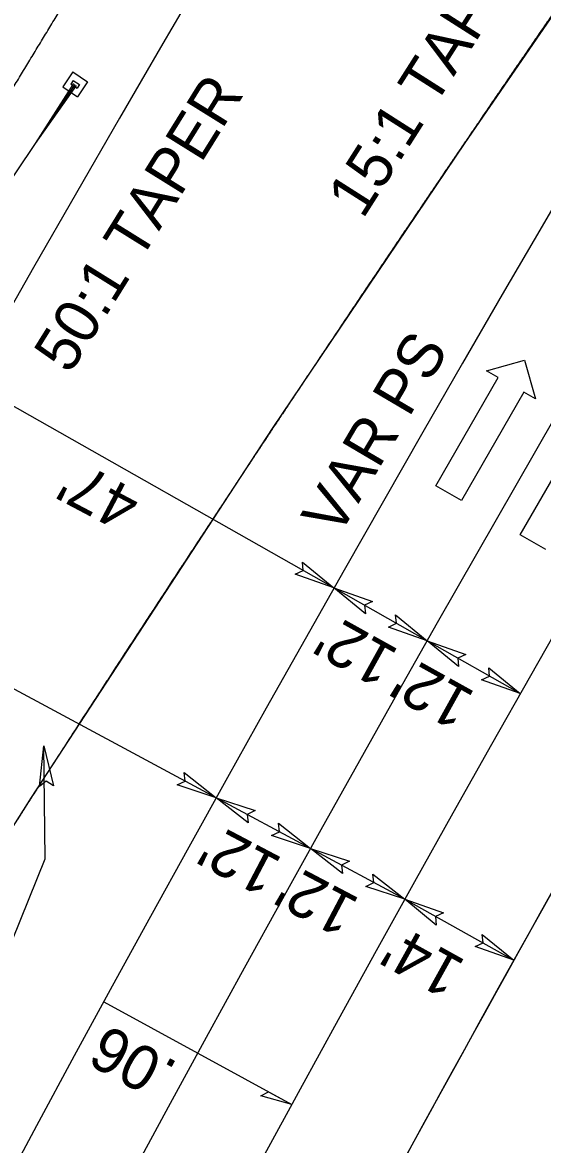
# Model space of a CAD drawing. Extents: x 2389694 to 2405615, y 546931 to 573532.
# Drawn here: x 2395690.8 to 2395749, y 557120.4 to 557246.1 of the extents above; entities that cross this region are included whole.
import ezdxf

# ---------------------------------------------------------------- set-up
doc = ezdxf.new("R2010")
doc.units = 0
for name, color, linetype in [('Prop Cable Guiderail Anchor Unit CELL', 7, 'Continuous'), ('Prop Dimension', 7, 'Continuous'), ('Prop Dimension Text', 7, 'Continuous'), ('Prop DSN Text', 7, 'Continuous'), ('Prop EOT', 7, 'Continuous'), ('Prop Guardrail', 7, 'Continuous'), ('Prop Horizontal Alignment', 7, 'Continuous'), ('Prop Lane Arrow Through CELL', 7, 'Continuous'), ('Prop Lane Lines', 7, 'Continuous'), ('Prop SBG', 7, 'Continuous'), ('Prop Super Arrow 1 Lane CELL', 7, 'Continuous'), ('Prop Superelevation Label', 7, 'Continuous')]:
    doc.layers.add(name, color=color, linetype=linetype)

msp = doc.modelspace()

# ---------------------------------------------------------------- linework, layer by layer
at = {"layer": 'Prop Cable Guiderail Anchor Unit CELL'}
for p, q in [((2395696.4, 557240.55), (2395695.28, 557238.89)), ((2395696.4, 557240.55), (2395698.06, 557239.43)), ((2395692.21, 557232.52), (2395696.51, 557239.27)), ((2395692.21, 557232.52), (2395696.67, 557239.16)), ((2395692.21, 557232.52), (2395696.83, 557239.03)), ((2395695.28, 557238.89), (2395696.94, 557237.77)), ((2395696.46, 557239.6), (2395696.18, 557239.19)), ((2395696.18, 557239.19), (2395696.88, 557238.72)), ((2395696.46, 557239.6), (2395697.16, 557239.14)), ((2395697.16, 557239.14), (2395696.88, 557238.72)), ((2395698.06, 557239.43), (2395696.94, 557237.77)), ((2395683.28, 557219.25), (2395692.21, 557232.52)), ((2395692.21, 557232.52), (2395692.21, 557232.52))]:
    msp.add_line(p, q, dxfattribs=at)
at = {"layer": 'Prop Dimension'}
for p, q in [((2395725.67, 557182.76), (2395684.78, 557205.93)), ((2395736.11, 557176.84), (2395725.67, 557182.76)), ((2395712.46, 557159.25), (2395671.06, 557181.49)), ((2395746.55, 557170.92), (2395736.11, 557176.84)), ((2395723.04, 557153.57), (2395712.46, 557159.25)), ((2395733.61, 557147.9), (2395723.04, 557153.57)), ((2395733.61, 557147.9), (2395745.82, 557141.05))]:
    msp.add_line(p, q, dxfattribs=at)
for points in [[(2395722.14, 557185.65), (2395725.67, 557182.76), (2395721.34, 557184.29), (2395722.23, 557184.7)], [(2395729.2, 557179.86), (2395725.67, 557182.76), (2395730, 557181.22), (2395729.1, 557180.81)], [(2395732.58, 557179.73), (2395736.11, 557176.84), (2395731.78, 557178.37), (2395732.67, 557178.79)], [(2395739.64, 557173.95), (2395736.11, 557176.84), (2395740.44, 557175.3), (2395739.54, 557174.89)], [(2395743.02, 557173.82), (2395746.55, 557170.92), (2395742.22, 557172.46), (2395743.11, 557172.87)], [(2395692.66, 557160.52), (2395693.17, 557165.06), (2395694.23, 557160.59), (2395693.4, 557161.12)], [(2395708.87, 557162.07), (2395712.46, 557159.25), (2395708.1, 557160.69), (2395708.98, 557161.12)], [(2395716.06, 557156.44), (2395712.46, 557159.25), (2395716.83, 557157.82), (2395715.94, 557157.38)], [(2395719.44, 557156.39), (2395723.04, 557153.57), (2395718.67, 557155.01), (2395719.56, 557155.44)], [(2395726.63, 557150.76), (2395723.04, 557153.57), (2395727.4, 557152.14), (2395726.52, 557151.71)], [(2395730.01, 557150.71), (2395733.61, 557147.9), (2395729.24, 557149.33), (2395730.13, 557149.77)], [(2395737.14, 557145), (2395733.61, 557147.9), (2395737.94, 557146.36), (2395737.04, 557145.95)], [(2395742.29, 557143.95), (2395745.82, 557141.05), (2395741.49, 557142.59), (2395742.38, 557143)]]:
    msp.add_lwpolyline(points, close=True, dxfattribs=at)
at = {"layer": 'Prop DSN Text'}
for p, q in [((2395693.29, 557152.41), (2395693.17, 557165.06)), ((2395688.7, 557141.04), (2395693.29, 557152.41))]:
    msp.add_line(p, q, dxfattribs=at)
at = {"layer": 'Prop EOT'}
for centre, radius, start, end in [((2398729.82, 555480.32), 3559, 136.54853, 163.17888), ((2398729.82, 555480.32), 3523, 136.54853, 169.40696), ((2398729.82, 555480.32), 3453, 136.54853, 155.44499), ((2398729.82, 555480.32), 3429, 136.54853, 155.44499), ((2398729.83, 555480.34), 3415, 150.73536, 155.44499)]:
    msp.add_arc(centre, radius, start, end, dxfattribs=at)
for points in [[(2395682.12, 557226.17), (2395682.58, 557226.95), (2395683.05, 557227.73), (2395683.52, 557228.5), (2395683.98, 557229.28), (2395684.45, 557230.06), (2395684.92, 557230.83), (2395685.38, 557231.61), (2395685.85, 557232.39), (2395686.32, 557233.16), (2395686.79, 557233.94), (2395687.26, 557234.71), (2395687.72, 557235.49), (2395688.19, 557236.27), (2395688.66, 557237.04), (2395689.13, 557237.82), (2395689.6, 557238.59), (2395690.07, 557239.37), (2395690.54, 557240.14), (2395691.01, 557240.92), (2395691.48, 557241.69), (2395691.95, 557242.47), (2395692.42, 557243.24), (2395692.89, 557244.02), (2395693.36, 557244.79), (2395693.83, 557245.56), (2395694.3, 557246.34), (2395694.77, 557247.11), (2395695.24, 557247.89), (2395695.72, 557248.66), (2395696.19, 557249.43), (2395696.66, 557250.21), (2395697.13, 557250.98), (2395697.6, 557251.75), (2395698.08, 557252.53), (2395698.55, 557253.3), (2395699.02, 557254.07), (2395699.5, 557254.85), (2395699.97, 557255.62), (2395700.44, 557256.39), (2395700.92, 557257.16), (2395701.39, 557257.93), (2395701.86, 557258.71), (2395702.34, 557259.48), (2395702.81, 557260.25), (2395703.29, 557261.02), (2395703.76, 557261.79), (2395704.24, 557262.57), (2395704.71, 557263.34), (2395705.19, 557264.11), (2395705.66, 557264.88), (2395706.14, 557265.65), (2395706.62, 557266.42), (2395707.09, 557267.19), (2395707.57, 557267.96), (2395708.05, 557268.73), (2395708.52, 557269.5), (2395709, 557270.27), (2395709.48, 557271.04), (2395709.96, 557271.81), (2395710.43, 557272.58), (2395710.91, 557273.35), (2395711.39, 557274.12), (2395711.87, 557274.89), (2395712.35, 557275.66), (2395712.83, 557276.43), (2395713.3, 557277.2), (2395713.78, 557277.97), (2395714.26, 557278.74), (2395714.74, 557279.5), (2395715.22, 557280.27), (2395715.7, 557281.04), (2395716.18, 557281.81), (2395717.14, 557283.35)], [(2395759.96, 557261.18), (2395759.56, 557260.61), (2395759.16, 557260.03), (2395758.76, 557259.46), (2395758.36, 557258.88), (2395757.96, 557258.31), (2395757.57, 557257.74), (2395757.17, 557257.17), (2395756.77, 557256.59), (2395756.38, 557256.02), (2395755.98, 557255.45), (2395755.58, 557254.87), (2395755.18, 557254.3), (2395754.79, 557253.72), (2395754.39, 557253.15), (2395753.99, 557252.57), (2395753.6, 557252), (2395753.2, 557251.42), (2395752.8, 557250.85), (2395752.41, 557250.28), (2395752.01, 557249.7), (2395751.61, 557249.13), (2395751.22, 557248.56), (2395750.82, 557247.98), (2395750.43, 557247.4), (2395750.03, 557246.82), (2395749.64, 557246.25), (2395749.24, 557245.68), (2395748.84, 557245.1), (2395748.45, 557244.53), (2395748.06, 557243.95), (2395747.66, 557243.37), (2395747.27, 557242.8), (2395746.87, 557242.22), (2395746.47, 557241.65), (2395746.08, 557241.07), (2395745.68, 557240.49), (2395745.29, 557239.92), (2395744.9, 557239.34), (2395744.5, 557238.76), (2395744.11, 557238.19), (2395743.71, 557237.61), (2395743.32, 557237.04), (2395742.93, 557236.46), (2395742.53, 557235.88), (2395742.14, 557235.31), (2395741.75, 557234.72), (2395741.35, 557234.15), (2395740.96, 557233.58), (2395740.57, 557232.99), (2395740.18, 557232.42), (2395739.78, 557231.84), (2395739.39, 557231.26), (2395739, 557230.69), (2395738.6, 557230.1), (2395738.21, 557229.53), (2395737.82, 557228.96), (2395737.43, 557228.37), (2395737.04, 557227.8), (2395736.64, 557227.21), (2395736.25, 557226.64), (2395735.86, 557226.06), (2395735.47, 557225.48), (2395735.08, 557224.9), (2395734.68, 557224.32), (2395734.3, 557223.74), (2395733.91, 557223.17), (2395733.51, 557222.59), (2395733.12, 557222.01), (2395732.73, 557221.43), (2395732.34, 557220.85), (2395731.95, 557220.27), (2395731.56, 557219.69), (2395731.17, 557219.11), (2395730.78, 557218.54)], [(2395730.78, 557218.54), (2395730.39, 557217.95), (2395730, 557217.37), (2395729.61, 557216.8), (2395729.22, 557216.21), (2395728.83, 557215.64), (2395728.44, 557215.05), (2395728.05, 557214.47), (2395727.66, 557213.9), (2395727.27, 557213.31), (2395726.88, 557212.73), (2395726.49, 557212.15), (2395726.11, 557211.57), (2395725.72, 557210.99), (2395725.33, 557210.41), (2395724.94, 557209.83), (2395724.55, 557209.25), (2395724.16, 557208.67), (2395723.78, 557208.09), (2395723.39, 557207.5), (2395723, 557206.92), (2395722.61, 557206.35), (2395722.22, 557205.76), (2395721.84, 557205.18), (2395721.45, 557204.6), (2395721.06, 557204.02), (2395720.68, 557203.44), (2395720.29, 557202.85), (2395719.9, 557202.27), (2395719.51, 557201.69), (2395719.12, 557201.11), (2395718.74, 557200.53), (2395718.35, 557199.94), (2395717.97, 557199.36), (2395717.58, 557198.78), (2395717.19, 557198.19), (2395716.81, 557197.61), (2395716.42, 557197.03), (2395716.03, 557196.45), (2395715.65, 557195.87), (2395715.26, 557195.28), (2395714.88, 557194.7), (2395714.49, 557194.12), (2395714.11, 557193.53), (2395713.72, 557192.95), (2395713.33, 557192.36), (2395712.95, 557191.78), (2395712.57, 557191.2), (2395712.18, 557190.61), (2395711.8, 557190.03), (2395711.42, 557189.45), (2395711.03, 557188.86), (2395710.65, 557188.28), (2395710.26, 557187.69), (2395709.88, 557187.11), (2395709.49, 557186.53), (2395709.11, 557185.94), (2395708.72, 557185.36), (2395708.34, 557184.77), (2395707.96, 557184.19), (2395707.57, 557183.61), (2395707.19, 557183.02), (2395706.81, 557182.44), (2395706.43, 557181.85), (2395706.04, 557181.26), (2395705.66, 557180.68), (2395705.27, 557180.09), (2395704.89, 557179.51), (2395704.51, 557178.93), (2395704.13, 557178.34), (2395703.75, 557177.75), (2395703.36, 557177.16), (2395702.98, 557176.58), (2395702.6, 557176), (2395702.21, 557175.41)], [(2395702.21, 557175.41), (2395701.84, 557174.82), (2395701.46, 557174.24), (2395701.07, 557173.65), (2395700.69, 557173.07), (2395700.31, 557172.48), (2395699.93, 557171.89), (2395699.55, 557171.31), (2395699.16, 557170.72), (2395698.79, 557170.13), (2395698.41, 557169.55), (2395698.02, 557168.96), (2395697.64, 557168.38), (2395697.26, 557167.78), (2395696.88, 557167.2), (2395696.5, 557166.62), (2395696.12, 557166.02), (2395695.74, 557165.44), (2395695.36, 557164.85), (2395694.98, 557164.26), (2395694.6, 557163.68), (2395694.22, 557163.09), (2395693.84, 557162.5), (2395693.47, 557161.92), (2395693.08, 557161.32), (2395692.71, 557160.74), (2395692.33, 557160.14), (2395691.95, 557159.56), (2395691.57, 557158.98), (2395691.19, 557158.38), (2395690.81, 557157.8), (2395690.43, 557157.2), (2395690.06, 557156.62), (2395689.68, 557156.03), (2395689.3, 557155.44), (2395688.92, 557154.85), (2395688.55, 557154.27), (2395688.17, 557153.67), (2395687.79, 557153.09), (2395687.41, 557152.49), (2395687.03, 557151.91), (2395686.66, 557151.32), (2395686.28, 557150.73), (2395685.9, 557150.14), (2395685.52, 557149.54), (2395685.15, 557148.96), (2395684.77, 557148.37), (2395684.39, 557147.78), (2395684.02, 557147.19), (2395683.65, 557146.6), (2395683.27, 557146.01), (2395682.89, 557145.42), (2395682.51, 557144.83), (2395682.14, 557144.24), (2395681.77, 557143.65), (2395681.39, 557143.06), (2395681.01, 557142.47), (2395680.64, 557141.88), (2395680.26, 557141.28), (2395679.89, 557140.7), (2395679.51, 557140.1), (2395679.14, 557139.51), (2395678.76, 557138.93), (2395678.39, 557138.33), (2395678.01, 557137.74), (2395677.64, 557137.14), (2395677.26, 557136.56), (2395676.89, 557135.97), (2395676.51, 557135.37), (2395676.14, 557134.78), (2395675.77, 557134.19), (2395675.39, 557133.6), (2395675.02, 557133.01), (2395674.27, 557131.82)]]:
    msp.add_spline(points, degree=3, dxfattribs=at)
at = {"layer": 'Prop Guardrail'}
for p, q in [((2395759.96, 557261.18), (2395740.33, 557232.6)), ((2395740.33, 557232.6), (2395718.75, 557200.6)), ((2395718.75, 557200.6), (2395691.74, 557159.27)), ((2395691.74, 557159.27), (2395674.51, 557132.24))]:
    msp.add_line(p, q, dxfattribs=at)
msp.add_arc((2398729.82, 555480.32), 3415, 149.9922, 155.44499, dxfattribs=at)
at = {"layer": 'Prop Horizontal Alignment'}
msp.add_arc((2398729.82, 555480.32), 3500, 136.54853, 177.15578, dxfattribs=at)
at = {"layer": 'Prop Lane Arrow Through CELL'}
for p, q in [((2395742.78, 557207.07), (2395747.04, 557208.25)), ((2395747.04, 557208.25), (2395748.24, 557203.93)), ((2395744.08, 557206.32), (2395742.78, 557207.07)), ((2395737.1, 557194.19), (2395744.08, 557206.32)), ((2395746.94, 557204.67), (2395739.96, 557192.54)), ((2395748.24, 557203.93), (2395746.94, 557204.67)), ((2395746.55, 557188.71), (2395753.54, 557200.84)), ((2395739.96, 557192.54), (2395737.1, 557194.19)), ((2395749.41, 557187.06), (2395746.55, 557188.71))]:
    msp.add_line(p, q, dxfattribs=at)
at = {"layer": 'Prop Lane Lines'}
for radius, end in [(3547, 169.40696), (3535, 169.40696), (3441, 155.44499)]:
    msp.add_arc((2398729.82, 555480.32), radius, 136.54853, end, dxfattribs=at)
at = {"layer": 'Prop SBG'}
msp.add_arc((2398729.82, 555480.32), 3415, 149.9922, 155.44499, dxfattribs=at)
at = {"layer": 'Prop Super Arrow 1 Lane CELL'}
msp.add_line((2395699.87, 557136.41), (2395720.93, 557124.9), dxfattribs=at)
msp.add_lwpolyline([(2395720.93, 557124.9), (2395717.48, 557125.88), (2395718.34, 557126.32)], close=True, dxfattribs=at)

# ---------------------------------------------------------------- texts
at = {"layer": 'Prop Dimension Text'}
for s, rotation, p in [('15:1 TAPER', 57.531, (2395728.9, 557223.97)), ('50:1 TAPER', 58.1202, (2395696.04, 557206.57)), ('VAR PS', 59.4965, (2395726.14, 557188.3)), ("47'", 152.1807, (2395704.3, 557193.28)), ("12'", 150.9193, (2395733.12, 557175.73)), ("12'", 150.9193, (2395741.68, 557170.98)), ("12'", 152.2202, (2395720.08, 557152.4)), ("12'", 152.2202, (2395728.74, 557147.85)), ("14'", 150.9193, (2395740.61, 557140.92))]:
    msp.add_text(s, height=5, rotation=rotation, dxfattribs=at).set_placement(p)
at = {"layer": 'Prop Superelevation Label'}
msp.add_text('.06', height=5, rotation=151.3398, dxfattribs=at).set_placement((2395708.39, 557129.48))

doc.saveas('drawing.dxf')
